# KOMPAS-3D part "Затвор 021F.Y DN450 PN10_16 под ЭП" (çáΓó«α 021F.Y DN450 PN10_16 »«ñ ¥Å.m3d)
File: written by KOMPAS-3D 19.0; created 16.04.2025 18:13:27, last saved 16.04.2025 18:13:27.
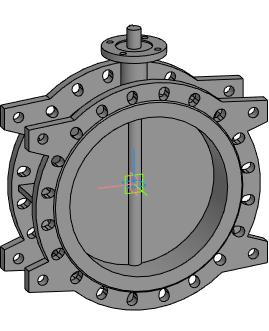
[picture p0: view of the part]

Document properties: Автор: Евгений; Полное имя файла: E:\Dendor Работа Сачек\3D для проекитирвщиков\1.6 Тип 021F.Y Затвор дисковый поворотный фланцевый\stp_Тип 021F.Y Затвор  DN40 PN10_16 под ЭП\Затвор 021F.Y DN450 PN10_16 под ЭП.m3d

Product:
- Part/product: Затвор 021F.Y DN450 PN10_16 под ЭП

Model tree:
1. Операция без истории:1  (labels: Затвор 021F.Y DN450 PN10_16 под ЭП)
